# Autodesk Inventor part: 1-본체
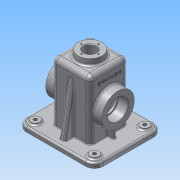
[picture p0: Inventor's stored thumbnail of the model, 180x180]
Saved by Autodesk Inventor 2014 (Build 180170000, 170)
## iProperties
Created: 2015-12
Part Number: 1-본체
Material: 알루미늄 6061
Document SubType Name: Modeling
Designer: Administrator
Density: 2.71 g/cm^3
Appearance: 알루미늄 - 평지
Mass: 770.297 g
Surface Area: 920.863 cm^2
Volume: 284.243 cm^3
Author: Administrator
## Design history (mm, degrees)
sketch "스케치1"
  geometry: L1 (65, -57.5)-(-65, -57.5); L2 (-65, -57.5)-(-65, 57.5); L3 (-65, 57.5)-(65, 57.5); L4 (65, 57.5)-(65, -57.5); L5 (65, -57.5)-(-65, 57.5); L6 (-65, -57.5)-(65, 57.5); 1 further point
  constraints: 12 end point, 2 midpoint, 2 parallel, 1 horizontal, 1 perpendicular
  dimensions: "d0" = 130 distance of L2.end L3.end; "d1" = 115 distance of L1.end L2.end
extrude "돌출1" new body sketch "스케치1" distance "d2" = 8; taper "d3" = 0 deg
node "작업 평면1"
sketch "스케치2"
  geometry: L1 (32.5, -32.5)-(-32.5, -32.5); L2 (-32.5, -32.5)-(-32.5, 32.5); L3 (-32.5, 32.5)-(32.5, 32.5); L4 (32.5, 32.5)-(32.5, -32.5); L5 (32.5, -32.5)-(-32.5, 32.5); L6 (-32.5, -32.5)-(32.5, 32.5); 1 further point
  constraints: 12 end point, 2 midpoint, 2 parallel, 1 horizontal, 1 perpendicular
  dimensions: "d5" = 65 distance of L2.end L3.end; "d6" = 65 distance of L1.end L2.end
extrude "돌출2" join sketch "스케치2" distance "d7" = 108; taper "d8" = 0 deg
fillet "모깎기1" dims "d9" = 15
sketch "스케치3"
  geometry: C1 r 7.5 at (-50, 42.5); A1 r 15 centre (-50, 42.5) between (-50, 57.5) and (-65, 42.5) reference; 1 further point
  constraints: 1 centre point, 1 coincident
  dimensions: "d10" = 15 diameter of C1
extrude "돌출3" join sketch "스케치3" distance "d11" = 3; taper "d12" = 0 deg
sketch "스케치4"
  geometry: C1 r 7.5 at (0, 0) reference; C2 r 3 at (0, 0); 1 further point
  constraints: 1 centre point, 1 coincident
  dimensions: "d13" = 6 diameter of C2
extrude "돌출4" cut sketch "스케치4" distance "d14" = 22; taper "d15" = 0 deg
feature "쉘1" dims "d23" = 8, "d24" = 5
sketch "스케치5"
  geometry: L1 (50, 57.5)-(-50, 57.5) reference; L2 (-65, 42.5)-(-65, -42.5) reference; L3 (-50, -57.5)-(50, -57.5) reference; L4 (65, -42.5)-(65, 42.5) reference; L5 (-50, 52.5)-(50, 52.5); L6 (60, 42.5)-(60, -42.5); L7 (50, -52.5)-(-50, -52.5); L8 (-60, -42.5)-(-60, 42.5); A1 r 15 centre (50, 42.5) between (65, 42.5) and (50, 57.5) reference; A2 r 15 centre (-50, 42.5) between (-50, 57.5) and (-65, 42.5) reference; A3 r 15 centre (-50, -42.5) between (-65, -42.5) and (-50, -57.5) reference; A4 r 15 centre (50, -42.5) between (50, -57.5) and (65, -42.5) reference; A5 r 10 centre (50, 42.5) between (60, 42.5) and (50, 52.5); A6 r 10 centre (50, -42.5) between (50, -52.5) and (60, -42.5); A7 r 10 centre (-50, -42.5) between (-60, -42.5) and (-50, -52.5); A8 r 10 centre (-50, 42.5) between (-50, 52.5) and (-60, 42.5); 1 further point
  constraints: 8 end point, 8 point on circle, 4 centre point, 7 other
  dimensions: "d16" = 5 distance between parallel lines of L1 L5
sketch "스케치6"
  geometry: L1 (-8, -10)-(-8, 75) reference; C1 r 27.5 at (45, 32.5); 2 further points
  constraints: 1 centre point, 1 horizontal alignment
  dimensions: "d19" = 55 diameter of C1; "d97" = 53 distance from line of L1 C1.centre
extrude "돌출6" join sketch "스케치6" distance "d21" = 15; taper "d22" = 0 deg
sketch "스케치7"
  geometry: C1 r 27.5 at (0, 0) reference; C2 r 17.5 at (0, 0); 1 further point
  constraints: 1 centre point, 1 coincident
  dimensions: "d25" = 35 diameter of C2
extrude "돌출7" cut sketch "스케치7" distance "d26" = 17; taper "d27" = 0 deg
sketch "스케치8"
  geometry: C1 r 17.5 at (0, 0) reference; C2 r 15 at (0, 0); 1 further point
  constraints: 1 centre point, 1 coincident
  dimensions: "d28" = 30 diameter of C2
extrude "돌출8" cut sketch "스케치8" distance "d29" = 3; taper "d30" = 0 deg
sketch "스케치9" dims "d31" = 42
  geometry: C1 r 17.5 at (0, 0) reference; C2 r 27.5 at (0, 0) reference; 3 further points
  constraints: 2 horizontal alignment, 1 coincident, 2 other
hole "구멍1" sketch "스케치9" at (21, 0) diameter "d32" = 3.242; stored, may be unused: countersink angle "d36" = 90 deg, drill point angle "d38" = 118 deg; dims "d33" = 8, "d34" = 4, "d35" = 2, "d37" = 10
fillet "모깎기2" dims "d42" = 8
fillet "모깎기3" dims "d43" = 8
node "작업 평면2"
sketch "스케치10"
  geometry: C1 r 20 at (0, 0); 1 further point
  constraints: 1 centre point, 1 coincident
  dimensions: "d46" = 40 diameter of C1
extrude "돌출9" join sketch "스케치10" stored distance "d47" = 3; taper "d48" = 5 deg
sketch "스케치11"
  geometry: C1 r 20 at (0, 0) reference; C2 r 10.5 at (0, 0)
  constraints: 1 centre point, 1 coincident
  dimensions: "d49" = 21 diameter of C2
extrude "돌출10" cut sketch "스케치11" distance "d50" = 45.25; taper "d51" = 0 deg
sketch "스케치12" dims "d52" = 29
  geometry: C1 r 10.5 at (0, 0) reference; C2 r 20 at (0, 0) reference; 2 further points
  constraints: 2 horizontal alignment, 1 coincident, 2 other
hole "구멍2" sketch "스케치12" at (-14.5, 0) diameter "d53" = 2.459; stored, may be unused: countersink angle "d57" = 90 deg, drill point angle "d59" = 118 deg; dims "d54" = 7, "d55" = 4, "d56" = 2, "d58" = 9
node "작업 평면3"
sketch "스케치13"
  geometry: L1 (-30.808, 102.662)-(-30.808, 8); L2 (-57.5, 0)-(-57.5, 8) reference; L3 (-30.808, 8)-(-47.5, 8); L4 (-47.5, 8)-(-30.808, 102.662); L5 (-57.5, 8)-(-42.5, 8) reference; 2 further points
  constraints: 6 end point, 1 collinear, 1 parallel, 1 perpendicular
  dimensions: "d65" = 10 distance from line of L2 L3.end; "d66" = 10 deg angle of L2 L4; "d67" = 94.66241 distance of L1.start L1.end
extrude "돌출11" join sketch "스케치13" stored distance "d68" = 10; taper "d69" = 0 deg
fillet "모깎기5" dims "d70" = 3
fillet "모깎기6" dims "d71" = 3
fillet "모깎기9" dims "d74" = 3
fillet "모깎기10" dims "d75" = 0.3
sketch "스케치14"
  geometry: L1 (32.5, 24.5)-(32.5, -24.5) reference; L2 (5, 44.454)-(5, 35.5) reference; L3 (32.5, 3)-(42.5, 3); L4 (42.5, 3)-(42.5, -3); L5 (42.5, -3)-(32.5, -3); L6 (32.5, -3)-(32.5, 3); L7 (27.5, -27.5)-(27.5, 27.5) reference; 4 further points
  constraints: 8 end point, 2 perpendicular, 2 point on line, 1 collinear, 1 horizontal alignment, 1 midpoint, 1 parallel
  dimensions: "d79" = 6 distance of L3.end L4.end; "d84" = 15 distance between parallel lines of L7 L4
extrude "돌출12" join sketch "스케치14" stored distance "d81" = 10; taper "d82" = 0 deg
fillet "모깎기14" dims "d83" = 3
fillet "모깎기15" dims "d85" = 3
fillet "모깎기16" dims "d86" = 1
sketch "스케치15"
  geometry: L1 (0, -8)-(91, -8) reference; L2 (-18, 4.5)-(-18, 44.5) reference; 2 further points
  constraints: 1 other
  dimensions: "d87" = 32.5 distance from line of L1 point (8, 24.5); "d88" = 26 distance from line of L2 point (8, 24.5)
feature "엠보싱1" sketch "스케치15" dims "d89" = 0.5, "d90" = 0
extrude "돌출13" join sketch "스케치5" distance "d91" = 2; taper "d92" = 0 deg
sketch "스케치16"
  geometry: C1 r 3 at (-50, 42.5); C2 r 3 at (-50, -42.5); C3 r 3 at (50, -42.5); C4 r 3 at (50, 42.5); A1 r 10 centre (-50, 42.5) between (-50, 52.5) and (-60, 42.5) reference; A2 r 10 centre (-50, -42.5) between (-60, -42.5) and (-50, -52.5) reference; A3 r 10 centre (50, -42.5) between (50, -52.5) and (60, -42.5) reference; A4 r 10 centre (50, 42.5) between (60, 42.5) and (50, 52.5) reference; 1 further point
  constraints: 4 centre point, 4 coincident, 3 equal radius
  dimensions: "d93" = 6 diameter of C1
extrude "돌출14" cut sketch "스케치16" distance "d94" = 40; taper "d95" = 0 deg
fillet "모깎기17" dims "d96" = 3
sketch "스케치17"
  geometry: L1 (27.5, -27.5)-(-27.5, -27.5); L2 (-27.5, -27.5)-(-27.5, 27.5); L3 (-27.5, 27.5)-(27.5, 27.5); L4 (27.5, 27.5)-(27.5, -27.5); L5 (27.5, -27.5)-(-27.5, 27.5); L6 (-27.5, -27.5)-(27.5, 27.5); 1 further point
  constraints: 12 end point, 2 midpoint, 2 parallel, 1 horizontal, 1 perpendicular
  dimensions: "d98" = 55 distance of L2.end L3.end; "d99" = 55 distance of L1.end L2.end
extrude "돌출15" cut sketch "스케치17" distance "d100" = 105; taper "d101" = 0 deg
fillet "모깎기18" dims "d102" = 3
fillet "모깎기19" dims "d103" = 3
chamfer "모따기1" distance "d104" = 1; stored, may be unused: second distance "d105" = 2, angle "d106" = 45 deg
node "솔리드1"
mirror "대칭1"
mirror "대칭2"
pattern_circular "원형 패턴1" dims angle "d40" = 360 deg
mirror "대칭3"
pattern_circular "원형 패턴2" dims angle "d61" = 360 deg
mirror "대칭4"
mirror "대칭5"
other parameters: "d4" = 0, "d63" = 0
